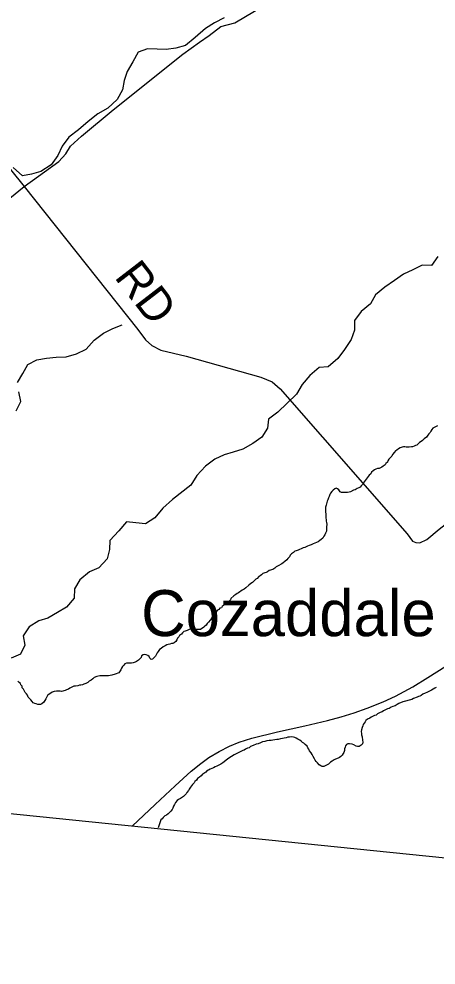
# Model space of a CAD drawing. Extents: x 0 to 1064, y 0 to 440.
# Drawn here: x 264.58 to 276.02, y 47.9 to 73.89 of the extents above; entities that cross this region are included whole.
import ezdxf

# ---------------------------------------------------------------- set-up
doc = ezdxf.new("R2010")
doc.units = 0
for name, color, linetype in [('GM_X_County', 7, 'Continuous'), ('GM_X_County_Road', 7, 'Continuous'), ('GM_X_County_Road_Text', 7, 'Continuous'), ('GM_X_Minor_River', 7, 'Continuous'), ('GM_X_Rail_Line', 7, 'Continuous'), ('GM_X_Township', 7, 'Continuous'), ('GM_X_Township_Road', 7, 'Continuous'), ('GM_X_Unincorporated_Text', 7, 'Continuous')]:
    doc.layers.add(name, color=color, linetype=linetype)

msp = doc.modelspace()

# ---------------------------------------------------------------- linework, layer by layer
at = {"layer": 'GM_X_County'}
msp.add_lwpolyline([(306.751, 47.903), (284.732, 50.122), (283.428, 50.199), (280.132, 50.441), (258.767, 52.625), (251.43, 53.311), (244.064, 54.077), (229.411, 55.772), (220.159, 56.563), (213.925, 57.196), (202.834, 58.322)], dxfattribs=at)
at = {"layer": 'GM_X_County_Road'}
msp.add_lwpolyline([(263.959, 70.214), (264.725, 69.283), (267.836, 65.353), (268.048, 65.073), (268.222, 64.914), (268.472, 64.785), (269.162, 64.626), (271.208, 64.05), (271.526, 63.921), (271.746, 63.731), (275.224, 59.745), (275.368, 59.548), (275.467, 59.503), (275.569, 59.499), (275.762, 59.59), (276.102, 59.876), (276.605, 60.264), (276.808, 60.382), (276.949, 60.245), (277.077, 60.094), (277.624, 59.397), (278.492, 58.275)], dxfattribs=at)
at = {"layer": 'GM_X_Minor_River'}
for points in [[(270.206, 73.915), (269.942, 73.779), (269.69, 73.619), (269.407, 73.375), (269.148, 73.16), (268.879, 73.085), (268.617, 73.047), (268.368, 73.057), (268.107, 73.067), (267.85, 72.968), (267.699, 72.709), (267.549, 72.444), (267.466, 72.19), (267.419, 71.936), (267.269, 71.671), (267.015, 71.432), (266.739, 71.278), (266.48, 71.07), (266.209, 70.843), (265.95, 70.641), (265.764, 70.395), (265.644, 70.135), (265.457, 69.877), (265.181, 69.693), (264.924, 69.618), (264.674, 69.58), (264.416, 69.802)], [(276.066, 67.363), (275.892, 67.116), (275.636, 67.121), (275.379, 66.997), (275.128, 66.873), (274.876, 66.701), (274.617, 66.517), (274.358, 66.308), (274.22, 66.062), (273.968, 65.847), (273.781, 65.601), (273.783, 65.339), (273.687, 65.086), (273.506, 64.809), (273.32, 64.557), (273.061, 64.336), (272.811, 64.316), (272.558, 64.095), (272.347, 63.843), (272.191, 63.578), (271.937, 63.333), (271.678, 63.088), (271.425, 62.898), (271.391, 62.649), (271.241, 62.403), (270.989, 62.23), (270.719, 62.071), (270.456, 61.984), (270.205, 61.915), (269.954, 61.797), (269.695, 61.601), (269.46, 61.343), (269.292, 61.085), (268.786, 60.692), (268.521, 60.447), (268.304, 60.189), (268.052, 60.017), (267.785, 60.051), (267.53, 60.074), (267.319, 59.828), (267.071, 59.565), (267.061, 59.316), (266.996, 59.061), (266.773, 58.81), (266.516, 58.698), (266.251, 58.484), (266.101, 58.237), (266.09, 57.976), (265.885, 57.73), (265.634, 57.588), (265.37, 57.428), (265.119, 57.36), (264.861, 57.187), (264.693, 56.941), (264.737, 56.691), (264.618, 56.444), (264.36, 56.333)], [(264.542, 63.9), (264.68, 64.147), (264.818, 64.394), (265.069, 64.524), (265.332, 64.568), (265.6, 64.601), (265.873, 64.609), (266.154, 64.689), (266.418, 64.813), (266.641, 65.064), (266.893, 65.255), (267.151, 65.384), (267.408, 65.483)], [(264.505, 63.123), (264.631, 63.383), (264.574, 63.645)], [(276.055, 62.709), (275.981, 62.679), (275.932, 62.65), (275.901, 62.608), (275.876, 62.566), (275.857, 62.53), (275.82, 62.488), (275.795, 62.452), (275.752, 62.404), (275.696, 62.35), (275.647, 62.308), (275.61, 62.278), (275.567, 62.249), (275.53, 62.213), (275.493, 62.183), (275.456, 62.171), (275.419, 62.154), (275.376, 62.136), (275.34, 62.131), (275.279, 62.126), (275.2, 62.127), (275.158, 62.134), (275.121, 62.134), (275.084, 62.123), (275.036, 62.111), (274.986, 62.082), (274.943, 62.046), (274.906, 62.022), (274.875, 61.986), (274.826, 61.92), (274.801, 61.878), (274.77, 61.842), (274.726, 61.794), (274.695, 61.752), (274.682, 61.716), (274.639, 61.674), (274.62, 61.638), (274.571, 61.608), (274.528, 61.573), (274.491, 61.555), (274.455, 61.543), (274.412, 61.538), (274.369, 61.52), (274.332, 61.503), (274.295, 61.473), (274.252, 61.437), (274.227, 61.395), (274.184, 61.359), (274.159, 61.317), (274.047, 61.173), (274.016, 61.137), (273.997, 61.101), (273.96, 61.065), (273.941, 61.029), (273.898, 61.005), (273.856, 60.988), (273.8, 60.958), (273.758, 60.947), (273.672, 60.9), (273.635, 60.894), (273.592, 60.883), (273.556, 60.877), (273.471, 60.878), (273.428, 60.885), (273.386, 60.898), (273.35, 60.953), (273.314, 60.984), (273.278, 60.997), (273.241, 60.985), (273.198, 60.944), (273.155, 60.908), (273.124, 60.866), (273.105, 60.83), (273.086, 60.769), (273.067, 60.733), (273.054, 60.678), (273.035, 60.642), (273.022, 60.606), (273.016, 60.57), (273.003, 60.533), (272.99, 60.479), (272.989, 60.443), (272.988, 60.394), (272.988, 60.358), (272.992, 60.278), (272.992, 60.224), (273.008, 60.096), (273.013, 60.059), (273.018, 60.011), (273.017, 59.926), (273.01, 59.871), (273.009, 59.822), (272.99, 59.762)], [(272.99, 59.762), (272.965, 59.714), (272.94, 59.678), (272.909, 59.63), (272.865, 59.594), (272.829, 59.564), (272.785, 59.528), (272.736, 59.505), (272.693, 59.487), (272.645, 59.47), (272.589, 59.446), (272.54, 59.423), (272.491, 59.405), (272.418, 59.37), (272.369, 59.359), (272.32, 59.335), (272.277, 59.318), (272.234, 59.3), (272.185, 59.283), (272.149, 59.265), (272.112, 59.235), (272.056, 59.2), (272.019, 59.164), (271.994, 59.116), (271.957, 59.068), (271.926, 59.032), (271.87, 58.984), (271.827, 58.948), (271.784, 58.924), (271.686, 58.865), (271.637, 58.836), (271.594, 58.8), (271.539, 58.77), (271.441, 58.736), (271.392, 58.706), (271.355, 58.688), (271.318, 58.677), (271.269, 58.653), (271.226, 58.623), (271.195, 58.588), (271.158, 58.57), (271.115, 58.522), (271.072, 58.498), (271.016, 58.445), (270.979, 58.409), (270.936, 58.379), (270.887, 58.337), (270.8, 58.266), (270.751, 58.23), (270.702, 58.2), (270.604, 58.129), (270.567, 58.111), (270.524, 58.076), (270.475, 58.04), (270.388, 57.968), (270.382, 57.932), (270.338, 57.884), (270.283, 57.849), (270.239, 57.801), (270.197, 57.789), (270.147, 57.754), (270.129, 57.717), (270.086, 57.7), (270.061, 57.664), (270.024, 57.652), (269.975, 57.598), (269.937, 57.556), (269.888, 57.496), (269.856, 57.424), (269.825, 57.376), (269.775, 57.322), (269.744, 57.286), (269.713, 57.238), (269.676, 57.214), (269.651, 57.178), (269.559, 57.119), (269.504, 57.114), (269.462, 57.114), (269.426, 57.121), (269.292, 57.123), (269.249, 57.118), (269.188, 57.094), (269.139, 57.077), (269.096, 57.059), (269.059, 57.024), (269.034, 56.987), (268.985, 56.958), (268.96, 56.916), (268.929, 56.88), (268.904, 56.838), (268.879, 56.789), (268.836, 56.748), (268.799, 56.736), (268.762, 56.73), (268.714, 56.719), (268.671, 56.702), (268.634, 56.696), (268.585, 56.673), (268.536, 56.643), (268.475, 56.601), (268.431, 56.566)], [(268.431, 56.566), (268.394, 56.518), (268.369, 56.482), (268.35, 56.439), (268.319, 56.385), (268.288, 56.349), (268.245, 56.307), (268.202, 56.29), (268.172, 56.327), (268.149, 56.376), (268.113, 56.407), (268.07, 56.419), (268.034, 56.432), (267.985, 56.421), (267.942, 56.391), (267.929, 56.349), (267.855, 56.277), (267.806, 56.235), (267.763, 56.224), (267.714, 56.206), (267.665, 56.195), (267.532, 56.197), (267.483, 56.174), (267.452, 56.138), (267.414, 56.102), (267.389, 56.054), (267.37, 56.011), (267.32, 55.927), (267.216, 55.892), (267.125, 55.863), (267.076, 55.852), (267.033, 55.847), (266.96, 55.842), (266.912, 55.849), (266.796, 55.85), (266.711, 55.827), (266.637, 55.798), (266.606, 55.762), (266.557, 55.727), (266.502, 55.697), (266.465, 55.667), (266.409, 55.632), (266.361, 55.614), (266.324, 55.603), (266.275, 55.591), (266.239, 55.586), (266.19, 55.574), (266.129, 55.563), (266.086, 55.558), (266.049, 55.54), (265.976, 55.511), (265.939, 55.481), (265.884, 55.458), (265.847, 55.44), (265.749, 55.417), (265.707, 55.424), (265.604, 55.426), (265.543, 55.415), (265.488, 55.397), (265.451, 55.373), (265.408, 55.344), (265.364, 55.308), (265.314, 55.212), (265.289, 55.169), (265.264, 55.127), (265.209, 55.08), (265.166, 55.062), (265.093, 55.063), (265.051, 55.076), (265.014, 55.083), (264.972, 55.108), (264.936, 55.139), (264.9, 55.188), (264.871, 55.225), (264.835, 55.262), (264.811, 55.311), (264.782, 55.354), (264.752, 55.391), (264.722, 55.44), (264.699, 55.483), (264.669, 55.52), (264.664, 55.562), (264.628, 55.599), (264.616, 55.636), (264.58, 55.667), (264.544, 55.704)], [(276.019, 55.527), (275.982, 55.51), (275.89, 55.45), (275.853, 55.433), (275.762, 55.392), (275.719, 55.368), (275.657, 55.339), (275.608, 55.303), (275.571, 55.291), (275.535, 55.274), (275.498, 55.256), (275.4, 55.221), (275.351, 55.198)], [(275.351, 55.198), (275.314, 55.186), (275.143, 55.14), (275.107, 55.129), (274.996, 55.082), (274.947, 55.058), (274.892, 55.023), (274.837, 55.005), (274.788, 54.982), (274.733, 54.952), (274.684, 54.941), (274.647, 54.923), (274.61, 54.9), (274.574, 54.882), (274.537, 54.858), (274.488, 54.841), (274.451, 54.823), (274.408, 54.8), (274.371, 54.77), (274.328, 54.758), (274.279, 54.729), (274.242, 54.711), (274.199, 54.681), (274.138, 54.652), (274.089, 54.622), (274.07, 54.58), (274.02, 54.508), (274.014, 54.472), (273.988, 54.43), (273.975, 54.363), (273.968, 54.32), (273.974, 54.266), (273.973, 54.223), (273.99, 54.168), (274.001, 54.083), (274.006, 54.028), (273.999, 53.98), (273.968, 53.938), (273.913, 53.908), (273.864, 53.903), (273.828, 53.916), (273.762, 53.947), (273.713, 53.966), (273.64, 53.979), (273.598, 53.98), (273.561, 53.962), (273.53, 53.926), (273.523, 53.89), (273.51, 53.842), (273.504, 53.793), (273.491, 53.745), (273.472, 53.709), (273.447, 53.666), (273.41, 53.631), (273.373, 53.601), (273.33, 53.583), (273.263, 53.56), (273.22, 53.542), (273.171, 53.507), (273.127, 53.471), (273.066, 53.417), (273.017, 53.394), (272.98, 53.37), (272.937, 53.353), (272.894, 53.353), (272.858, 53.372), (272.816, 53.403), (272.762, 53.453), (272.727, 53.496), (272.703, 53.532), (272.685, 53.569), (272.65, 53.631), (272.62, 53.686), (272.591, 53.729), (272.549, 53.79), (272.526, 53.833), (272.502, 53.87), (272.484, 53.919), (272.43, 53.956), (272.394, 53.993), (272.358, 54.018), (272.316, 54.049), (272.28, 54.08), (272.226, 54.111), (272.178, 54.13), (272.142, 54.155), (272.105, 54.162), (272.057, 54.175), (272.002, 54.163), (271.953, 54.158), (271.905, 54.141), (271.856, 54.135), (271.807, 54.124), (271.752, 54.113), (271.685, 54.102), (271.648, 54.096), (271.594, 54.091), (271.545, 54.08), (271.496, 54.074), (271.441, 54.069), (271.38, 54.058)], [(271.38, 54.058), (271.319, 54.041), (271.258, 54.029), (271.203, 54.006), (271.142, 53.983), (271.081, 53.965), (271.001, 53.936), (270.928, 53.901), (270.891, 53.871), (270.848, 53.86), (270.793, 53.83), (270.756, 53.807), (270.719, 53.795), (270.683, 53.777), (270.627, 53.748), (270.48, 53.677), (270.333, 53.582), (270.296, 53.553), (270.259, 53.529), (270.203, 53.487), (270.166, 53.457), (270.111, 53.422), (270.056, 53.392), (270.007, 53.363), (269.964, 53.345), (269.915, 53.316), (269.866, 53.298), (269.823, 53.281), (269.78, 53.251), (269.743, 53.245), (269.7, 53.204), (269.651, 53.168), (269.608, 53.144), (269.571, 53.102), (269.528, 53.067), (269.478, 53.025), (269.447, 52.983), (269.398, 52.941), (269.379, 52.905), (269.342, 52.863), (269.28, 52.791), (269.242, 52.737), (269.224, 52.701), (269.186, 52.641), (269.167, 52.604), (269.093, 52.533), (269.007, 52.473), (268.958, 52.45), (268.915, 52.42), (268.871, 52.366), (268.846, 52.312), (268.815, 52.264), (268.796, 52.215), (268.777, 52.179), (268.746, 52.131), (268.709, 52.095), (268.666, 52.06), (268.629, 52.018), (268.58, 52), (268.53, 51.958), (268.505, 51.916), (268.468, 51.893), (268.399, 51.668)]]:
    msp.add_lwpolyline(points, dxfattribs=at)
at = {"layer": 'GM_X_Rail_Line'}
msp.add_lwpolyline([(267.684, 51.719), (268.314, 52.316), (268.859, 52.826), (269.303, 53.228), (269.569, 53.442), (269.79, 53.602), (270.069, 53.766), (270.354, 53.912), (270.619, 54.02), (270.965, 54.138), (271.672, 54.305), (272.416, 54.475), (273.037, 54.619), (273.42, 54.721), (273.768, 54.829), (274.128, 54.958), (274.563, 55.134), (274.906, 55.289), (275.383, 55.543), (275.789, 55.796), (276.849, 56.472)], dxfattribs=at)
at = {"layer": 'GM_X_Township'}
msp.add_lwpolyline([(287.85, 124.199), (287.517, 120.482), (286.747, 113.278), (286.726, 112.97), (286.639, 111.696), (285.778, 105.953), (284.456, 96.847), (283.14, 81.291), (283.031, 79.941), (282.241, 70.19), (281.339, 61.996), (281.161, 60.312), (280.707, 55.955), (280.132, 50.441), (258.767, 52.625), (251.43, 53.311), (244.064, 54.077), (229.411, 55.772), (220.159, 56.563), (213.925, 57.196), (202.834, 58.322)], dxfattribs=at)
at = {"layer": 'GM_X_Township_Road'}
msp.add_lwpolyline([(244.064, 54.077), (248.997, 56.283), (249.011, 56.29), (253.229, 59.931), (264.725, 69.283), (265.67, 69.972), (265.863, 70.18), (265.993, 70.394), (266.291, 70.665), (267.166, 71.389), (269.074, 72.922), (269.528, 73.25), (269.799, 73.428), (270.117, 73.678), (270.502, 73.777), (272.515, 74.986), (275.194, 76.571), (278.103, 78.35), (279.553, 79.219)], dxfattribs=at)

# ---------------------------------------------------------------- texts
at = {"layer": 'GM_X_County_Road_Text'}
msp.add_text('RD', height=0.9091, rotation=307.6587, dxfattribs=at).set_placement((267.173, 66.795))
at = {"layer": 'GM_X_Unincorporated_Text'}
msp.add_text('Cozaddale', height=1.2636, rotation=0, dxfattribs=at).set_placement((267.93, 56.936))

doc.saveas('drawing.dxf')
